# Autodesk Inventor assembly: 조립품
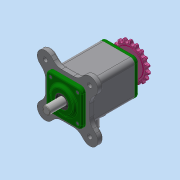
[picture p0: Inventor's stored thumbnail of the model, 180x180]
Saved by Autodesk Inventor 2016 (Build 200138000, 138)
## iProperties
Created: 2019-11
Part Number: 조립품
Material: 일반
Document SubType Name: Assembly
Designer: user
Author: user
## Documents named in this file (11)
- C:\Users\user\Desktop\491109V1003\조립품.iam
- C:\Users\user\Desktop\491109V1003\베어링 6203.ipt
- C:\Users\user\Desktop\491109V1003\본체.ipt
- C:\Users\user\Desktop\491109V1003\볼트 M4.ipt
- C:\Users\user\Desktop\491109V1003\부시.ipt
- C:\Users\user\Desktop\491109V1003\스프로킷.ipt
- C:\Users\user\Desktop\491109V1003\슬라이더.ipt
- C:\Users\user\Desktop\491109V1003\오일 실.ipt
- C:\Users\user\Desktop\491109V1003\커버.ipt
- C:\Users\user\Desktop\491109V1003\키 4 x 4 x 14.ipt
- C:\Users\user\Desktop\491109V1003\편심축.ipt
